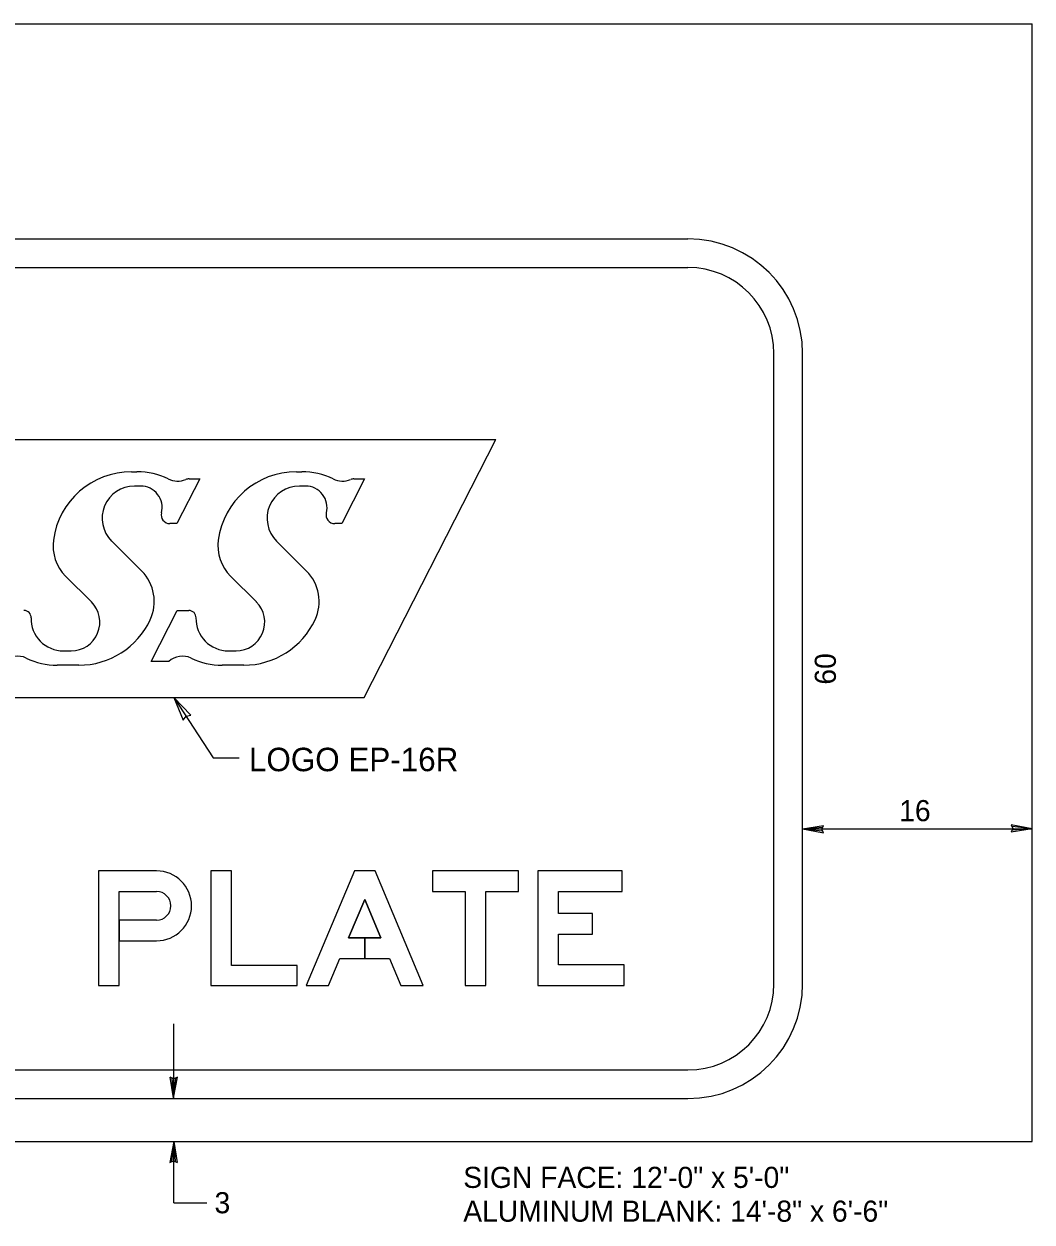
# Model space of a CAD drawing. Extents: x 60714 to 61340, y 9359 to 9750.
# Drawn here: x 60967.4 to 61101, y 9591.3 to 9750.1 of the extents above; entities that cross this region are included whole.
import ezdxf

# ---------------------------------------------------------------- set-up
doc = ezdxf.new("R2010")
doc.units = 0
for name, color, linetype in [('1', 7, 'Continuous'), ('2', 7, 'Continuous'), ('52', 7, 'Continuous'), ('GSBWFill', 7, 'Continuous'), ('SignPanel', 7, 'Continuous')]:
    doc.layers.add(name, color=color, linetype=linetype)

msp = doc.modelspace()

# ---------------------------------------------------------------- linework, layer by layer
at = {"layer": '1'}
for p, q in [((60987.23, 9660.83), (60992.47, 9652.83)), ((60992.47, 9652.83), (60995.91, 9652.83)), ((61070.57, 9643.41), (61100.97, 9643.41)), ((60987.23, 9607.63), (60987.23, 9617.52)), ((60987.23, 9593.82), (60987.23, 9601.93)), ((60987.23, 9593.82), (60991.64, 9593.82))]:
    msp.add_line(p, q, dxfattribs=at)
at = {"layer": '2'}
for p, q in [((60766.57, 9750.13), (61100.97, 9750.13)), ((61100.97, 9601.93), (61100.97, 9750.13)), ((60766.57, 9601.93), (61100.97, 9601.93))]:
    msp.add_line(p, q, dxfattribs=at)
at = {"layer": '52'}
for p, q in [((60987.23, 9660.83), (60988.48, 9657.79)), ((60989.5, 9658.46), (60987.23, 9660.83)), ((60988.48, 9657.79), (60988.86, 9658.34)), ((60988.86, 9658.34), (60989.5, 9658.46)), ((61070.57, 9643.41), (61073.35, 9643.85)), ((61073.13, 9643.37), (61073.35, 9643.85)), ((61100.97, 9643.41), (61098.21, 9643.95)), ((61098.21, 9643.95), (61098.41, 9643.46)), ((61070.57, 9643.41), (61073.23, 9643.6)), ((61070.57, 9643.41), (61073.33, 9642.88)), ((61070.57, 9643.41), (61073.22, 9643.13)), ((61073.33, 9642.88), (61073.13, 9643.37)), ((61098.41, 9643.46), (61098.19, 9642.97)), ((61100.97, 9643.41), (61098.19, 9642.97)), ((61100.97, 9643.41), (61098.31, 9643.23)), ((61100.97, 9643.41), (61098.32, 9643.69)), ((60987.22, 9607.71), (60986.78, 9610.48)), ((60987.26, 9610.26), (60986.78, 9610.48)), ((60987.22, 9607.71), (60987.03, 9610.37)), ((60987.22, 9607.71), (60987.75, 9610.47)), ((60987.22, 9607.71), (60987.5, 9610.36)), ((60987.75, 9610.47), (60987.26, 9610.26)), ((60987.23, 9601.93), (60986.7, 9599.17)), ((60987.23, 9601.93), (60986.95, 9599.28)), ((60987.23, 9601.93), (60987.67, 9599.15)), ((60987.23, 9601.93), (60987.42, 9599.27)), ((60986.7, 9599.17), (60987.19, 9599.37)), ((60987.19, 9599.37), (60987.67, 9599.15))]:
    msp.add_line(p, q, dxfattribs=at)
at = {"layer": 'GSBWFill'}
for p, q in [((60980.01, 9635.09), (60984.95, 9635.09)), ((60980.01, 9635.09), (60984.95, 9635.09)), ((60980.01, 9635.09), (60984.95, 9635.09)), ((60980.01, 9628.56), (60984.95, 9628.56))]:
    msp.add_line(p, q, dxfattribs=at)
for points in [[(60984.95, 9637.83), (60977.27, 9637.83), (60977.27, 9622.63), (60980.01, 9622.63), (60980.01, 9628.56)], [(60984.95, 9637.83), (60977.27, 9637.83), (60977.27, 9622.63), (60980.01, 9622.63), (60980.01, 9635.09)], [(60984.95, 9637.83), (60977.27, 9637.83), (60977.27, 9622.63), (60980.01, 9622.63), (60980.01, 9635.09)], [(60984.95, 9631.29), (60980.01, 9631.29), (60980.01, 9635.09)], [(60984.95, 9631.29), (60980.01, 9631.29), (60980.01, 9628.56), (60984.95, 9628.56)], [(60984.95, 9631.29), (60980.01, 9631.29), (60980.01, 9628.56), (60984.95, 9628.56)]]:
    msp.add_lwpolyline(points, dxfattribs=at)
for points in [[(61003.58, 9622.63), (61003.58, 9625.29), (60994.91, 9625.29), (60994.91, 9637.83), (60992.17, 9637.83), (60992.17, 9622.63)], [(61003.58, 9622.63), (61003.58, 9625.29), (60994.91, 9625.29), (60994.91, 9637.83), (60992.17, 9637.83), (60992.17, 9622.63)], [(61003.58, 9622.63), (61003.58, 9625.29), (60994.91, 9625.29), (60994.91, 9637.83), (60992.17, 9637.83), (60992.17, 9622.63)], [(61009.26, 9626.2), (61015.83, 9626.2), (61017.33, 9622.63), (61020.3, 9622.63), (61013.91, 9637.83), (61011.18, 9637.83), (61004.79, 9622.63), (61007.76, 9622.63)], [(61014.68, 9628.94), (61012.55, 9628.94), (61012.55, 9626.2), (61015.83, 9626.2), (61017.33, 9622.63), (61020.3, 9622.63), (61013.91, 9637.83), (61011.18, 9637.83), (61004.79, 9622.63), (61007.76, 9622.63), (61009.26, 9626.2), (61012.55, 9626.2), (61012.55, 9628.94), (61010.41, 9628.94), (61012.55, 9634.02)], [(61014.68, 9628.94), (61012.55, 9628.94), (61012.55, 9626.2), (61015.83, 9626.2), (61017.33, 9622.63), (61020.3, 9622.63), (61013.91, 9637.83), (61011.18, 9637.83), (61004.79, 9622.63), (61007.76, 9622.63), (61009.26, 9626.2), (61012.55, 9626.2), (61012.55, 9628.94), (61010.41, 9628.94), (61012.55, 9634.02)], [(61021.52, 9635.09), (61025.85, 9635.09), (61025.85, 9622.63), (61028.59, 9622.63), (61028.59, 9635.09), (61032.92, 9635.09), (61032.92, 9637.83), (61021.52, 9637.83)], [(61021.52, 9635.09), (61025.85, 9635.09), (61025.85, 9622.63), (61028.59, 9622.63), (61028.59, 9635.09), (61032.92, 9635.09), (61032.92, 9637.83), (61021.52, 9637.83)], [(61021.52, 9635.09), (61025.85, 9635.09), (61025.85, 9622.63), (61028.59, 9622.63), (61028.59, 9635.09), (61032.92, 9635.09), (61032.92, 9637.83), (61021.52, 9637.83)], [(61046.91, 9625.36), (61038.24, 9625.36), (61038.24, 9629.45), (61042.72, 9629.45), (61042.72, 9632.19), (61038.24, 9632.19), (61038.24, 9635.09), (61046.68, 9635.09), (61046.68, 9637.83), (61035.5, 9637.83), (61035.5, 9622.63), (61046.91, 9622.63)], [(61046.91, 9625.36), (61038.24, 9625.36), (61038.24, 9629.45), (61042.72, 9629.45), (61042.72, 9632.19), (61038.24, 9632.19), (61038.24, 9635.09), (61046.68, 9635.09), (61046.68, 9637.83), (61035.5, 9637.83), (61035.5, 9622.63), (61046.91, 9622.63)], [(61046.91, 9625.36), (61038.24, 9625.36), (61038.24, 9629.45), (61042.72, 9629.45), (61042.72, 9632.19), (61038.24, 9632.19), (61038.24, 9635.09), (61046.68, 9635.09), (61046.68, 9637.83), (61035.5, 9637.83), (61035.5, 9622.63), (61046.91, 9622.63)], [(61014.68, 9628.94), (61012.55, 9634.02), (61010.41, 9628.94)]]:
    msp.add_lwpolyline(points, close=True, dxfattribs=at)
for major_axis in [(0, 4.64), (0, 4.64), (0, 4.64), (0, 1.9), (0, 1.9), (0, 1.9)]:
    msp.add_ellipse((60984.95, 9633.19), major_axis=major_axis, ratio=0.999994, start_param=3.141593, end_param=6.283185, dxfattribs=at)
at = {"layer": 'SignPanel'}
for p, q in [((60812.17, 9721.63), (61055.37, 9721.63)), ((60812.17, 9717.83), (61055.37, 9717.83)), ((61066.77, 9622.83), (61066.77, 9706.43)), ((61070.57, 9622.83), (61070.57, 9706.43)), ((60921.52, 9695.03), (61029.91, 9695.03)), ((61012.48, 9660.83), (61029.91, 9695.03)), ((60981.64, 9690.76), (60982.36, 9690.76)), ((60990.68, 9689.8), (60987.66, 9683.88)), ((60989.26, 9689.8), (60990.68, 9689.8)), ((61003.5, 9690.76), (61004.22, 9690.76)), ((61012.53, 9689.8), (61009.51, 9683.88)), ((61011.11, 9689.8), (61012.53, 9689.8)), ((60982.85, 9688.86), (60982.03, 9688.86)), ((61004.7, 9688.86), (61003.88, 9688.86)), ((60987.66, 9683.88), (60986.71, 9683.88)), ((61009.51, 9683.88), (61008.56, 9683.88)), ((60979.01, 9681.56), (60982.99, 9677.58)), ((61000.86, 9681.56), (61004.84, 9677.58)), ((60976.32, 9673.49), (60972.91, 9676.91)), ((60998.18, 9673.49), (60994.76, 9676.91)), ((60984.26, 9665.58), (60987.71, 9672.35)), ((60987.71, 9672.35), (60989.24, 9672.35)), ((60972.61, 9667), (60973.64, 9667)), ((60994.46, 9667), (60995.49, 9667)), ((60974.66, 9665.1), (60971.8, 9665.1)), ((60986.57, 9665.58), (60984.26, 9665.58)), ((60996.51, 9665.1), (60993.65, 9665.1)), ((60919, 9660.83), (61012.48, 9660.83)), ((60812.17, 9611.43), (61055.37, 9611.43)), ((60812.17, 9607.63), (61055.37, 9607.63))]:
    msp.add_line(p, q, dxfattribs=at)
for centre, radius, start, end in [((61055.37, 9706.43), 15.2, 0, 90), ((61055.37, 9706.43), 11.4, 0, 90), ((60981.64, 9680.3), 10.45, 90, 172.3089), ((60982.36, 9681.25), 9.5, 64.0896, 90), ((60987.76, 9692.36), 2.85, 244.0896, 292.0347), ((60989.26, 9688.66), 1.14, 90, 112.0347), ((61003.49, 9680.3), 10.45, 90, 172.3089), ((61004.21, 9681.25), 9.5, 64.0896, 90), ((61009.61, 9692.36), 2.85, 244.0896, 292.0347), ((61011.11, 9688.66), 1.14, 90, 112.0347), ((60982.03, 9684.58), 4.28, 90, 225), ((60982.85, 9686), 2.85, 345.6915, 90), ((61003.88, 9684.58), 4.28, 90, 225), ((61004.7, 9686), 2.85, 345.6915, 90), ((60986.71, 9685.02), 1.14, 165.6915, 270), ((61008.56, 9685.02), 1.14, 165.6915, 270), ((60976.94, 9680.94), 5.7, 172.3089, 225), ((60998.79, 9680.94), 5.7, 172.3089, 225), ((60978.96, 9673.54), 5.7, 334.95, 45), ((61000.81, 9673.54), 5.7, 334.95, 45), ((60967.39, 9671.4), 0.95, 358.6665, 90), ((60973.64, 9670.8), 3.8, 270, 45), ((60989.24, 9671.4), 0.95, 358.6665, 90), ((60995.49, 9670.8), 3.8, 270, 45), ((60972.61, 9671.28), 4.28, 178.6665, 270), ((60974.66, 9675.55), 10.45, 270, 334.95), ((60994.46, 9671.28), 4.28, 178.6665, 270), ((60996.51, 9675.55), 10.45, 270, 334.95), ((60966.54, 9663.64), 2.66, 64.3795, 133.1892), ((60971.8, 9674.6), 9.5, 244.3795, 270), ((60988.39, 9663.64), 2.66, 64.3795, 133.1892), ((60993.65, 9674.6), 9.5, 244.3795, 270), ((61055.37, 9622.83), 15.2, 270, 0), ((61055.37, 9622.83), 11.4, 270, 0)]:
    msp.add_arc(centre, radius, start, end, dxfattribs=at)

# ---------------------------------------------------------------- texts
at = {"layer": '1'}
for s, height, rotation, p in [('60', 2.8, 90, (61074.98, 9662.52)), ('LOGO EP-16R', 3.1111, 0, (60997.2, 9651.04)), ('16', 2.8, 0, (61083.37, 9644.41)), ('3', 2.8, 0, (60992.64, 9592.42))]:
    msp.add_text(s, height=height, rotation=rotation, dxfattribs=at).set_placement(p)
at = {"layer": '2'}
for s, p in [('SIGN FACE: 12\'-0" x 5\'-0"', (61025.6, 9595.78)), ('ALUMINUM BLANK: 14\'-8" x 6\'-6"', (61025.6, 9591.3))]:
    msp.add_text(s, height=2.8, rotation=0, dxfattribs=at).set_placement(p)

doc.saveas('drawing.dxf')
